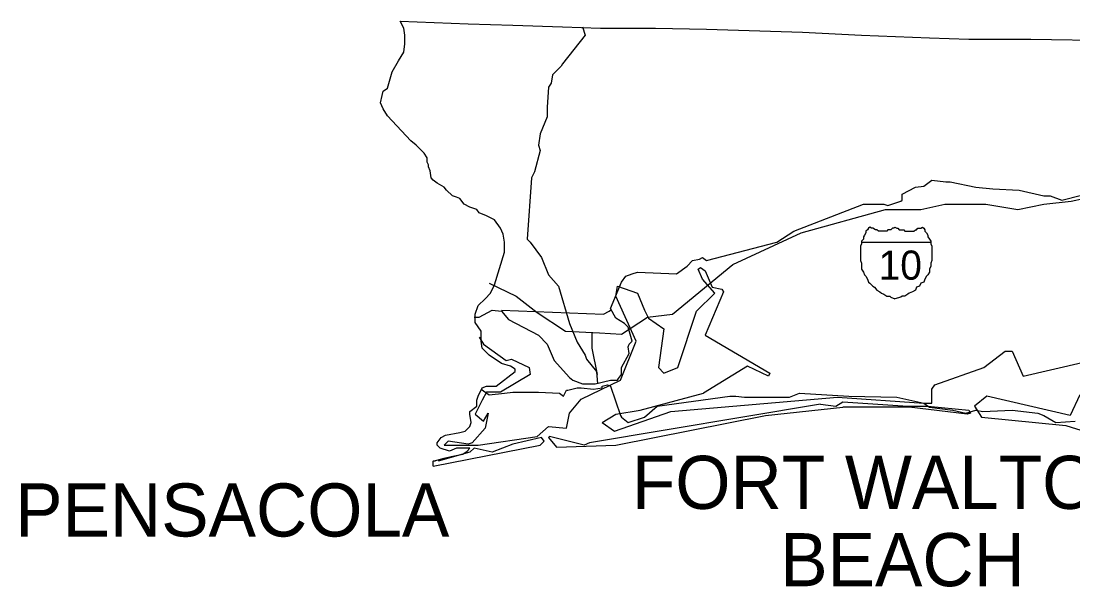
# Model space of a CAD drawing. Extents: x -820.2 to -798.1, y -2199.1 to -2182.2.
# Drawn here: x -808.86 to -807.968, y -2183.531 to -2183.051 of the extents above; entities that cross this region are included whole.
import ezdxf

# ---------------------------------------------------------------- set-up
doc = ezdxf.new("R2010")
doc.units = 0
for name, color, linetype in [('FLMap1', 7, 'Continuous'), ('FLMap2', 7, 'Continuous'), ('FLMap3', 7, 'Continuous'), ('TextMisc', 7, 'Continuous')]:
    doc.layers.add(name, color=color, linetype=linetype)

msp = doc.modelspace()

# ---------------------------------------------------------------- linework, layer by layer
at = {"layer": 'FLMap1'}
msp.add_line((-808.14733, -2183.23888), (-808.08878, -2183.23888), dxfattribs=at)
for points in [[(-808.11905, -2183.22598), (-808.12004, -2183.22697), (-808.12103, -2183.22697), (-808.12252, -2183.22846), (-808.12351, -2183.22846), (-808.125, -2183.22846), (-808.12599, -2183.22945), (-808.12699, -2183.22945), (-808.12847, -2183.22945), (-808.12947, -2183.22945), (-808.13195, -2183.22945), (-808.13294, -2183.22945), (-808.13443, -2183.22846), (-808.13542, -2183.22846), (-808.1379, -2183.22697), (-808.13889, -2183.22697), (-808.14038, -2183.22598), (-808.14137, -2183.22697), (-808.14237, -2183.22846), (-808.14385, -2183.22945), (-808.14385, -2183.23094), (-808.14485, -2183.23292), (-808.14584, -2183.23441), (-808.14584, -2183.2364), (-808.14733, -2183.23788), (-808.14733, -2183.24036), (-808.14832, -2183.24235), (-808.14832, -2183.24483), (-808.14832, -2183.24731), (-808.14832, -2183.24979), (-808.14832, -2183.25178), (-808.14832, -2183.25426), (-808.14733, -2183.25674), (-808.14733, -2183.25922), (-808.14733, -2183.2617), (-808.14584, -2183.26418), (-808.14485, -2183.26666), (-808.14385, -2183.26765), (-808.14237, -2183.27013), (-808.14137, -2183.27261), (-808.14038, -2183.27361), (-808.1379, -2183.27609), (-808.13641, -2183.27708), (-808.13443, -2183.27956), (-808.13195, -2183.28105), (-808.13046, -2183.28204), (-808.12847, -2183.28303), (-808.12599, -2183.28452), (-808.12351, -2183.28452), (-808.12252, -2183.28551), (-808.11905, -2183.287)], [(-808.11905, -2183.22598), (-808.11756, -2183.22697), (-808.11657, -2183.22697), (-808.11558, -2183.22846), (-808.11409, -2183.22846), (-808.11161, -2183.22846), (-808.11061, -2183.22945), (-808.10962, -2183.22945), (-808.10813, -2183.22945), (-808.10714, -2183.22945), (-808.10516, -2183.22945), (-808.10317, -2183.22945), (-808.10168, -2183.22846), (-808.10069, -2183.22846), (-808.0997, -2183.22697), (-808.09722, -2183.22697), (-808.09573, -2183.22598), (-808.09474, -2183.22697), (-808.09375, -2183.22846), (-808.09375, -2183.22945), (-808.09226, -2183.23094), (-808.09127, -2183.23292), (-808.09127, -2183.23441), (-808.08978, -2183.2364), (-808.08878, -2183.23788), (-808.08878, -2183.24036), (-808.08779, -2183.24235), (-808.08779, -2183.24483), (-808.08779, -2183.24731), (-808.08779, -2183.24979), (-808.08779, -2183.25178), (-808.08779, -2183.25426), (-808.08878, -2183.25674), (-808.08878, -2183.25922), (-808.08978, -2183.2617), (-808.08978, -2183.26418), (-808.09127, -2183.26666), (-808.09226, -2183.26765), (-808.09375, -2183.27013), (-808.09474, -2183.27261), (-808.09722, -2183.27361), (-808.09821, -2183.27609), (-808.10069, -2183.27708), (-808.10168, -2183.27956), (-808.10416, -2183.28105), (-808.10714, -2183.28204), (-808.10813, -2183.28303), (-808.11061, -2183.28452), (-808.11309, -2183.28452), (-808.11409, -2183.28551), (-808.11905, -2183.287)]]:
    msp.add_lwpolyline(points, dxfattribs=at)
at = {"layer": 'FLMap2'}
for points in [[(-808.51049, -2183.42889), (-808.51049, -2183.42443), (-808.50106, -2183.42195), (-808.49511, -2183.42046), (-808.48519, -2183.41847), (-808.48171, -2183.41599), (-808.47923, -2183.41351), (-808.49065, -2183.41351), (-808.4966, -2183.41599), (-808.50454, -2183.41351), (-808.50702, -2183.41103), (-808.50702, -2183.40905), (-808.50354, -2183.40458), (-808.50007, -2183.4026), (-808.48767, -2183.40012), (-808.4832, -2183.39912), (-808.47923, -2183.39516), (-808.47824, -2183.39168), (-808.47923, -2183.38474), (-808.47923, -2183.38226), (-808.47328, -2183.37779), (-808.47328, -2183.37283), (-808.47229, -2183.36936), (-808.46882, -2183.36241), (-808.46534, -2183.36092), (-808.46187, -2183.36092), (-808.45691, -2183.36092), (-808.44103, -2183.34852), (-808.44103, -2183.34654), (-808.445, -2183.34405), (-808.45244, -2183.34157), (-808.46286, -2183.33463), (-808.46882, -2183.32868), (-808.46981, -2183.32272), (-808.46981, -2183.31776), (-808.46981, -2183.31429), (-808.47477, -2183.30685), (-808.47477, -2183.2999), (-808.47229, -2183.29246), (-808.46634, -2183.287), (-808.46187, -2183.28204), (-808.4584, -2183.27509), (-808.44996, -2183.24731), (-808.44996, -2183.23888), (-808.45096, -2183.23193), (-808.45344, -2183.22697), (-808.4584, -2183.22002), (-808.46534, -2183.21655), (-808.4713, -2183.21407), (-808.47328, -2183.21109), (-808.47923, -2183.20911), (-808.4842, -2183.20663), (-808.48767, -2183.20167), (-808.49065, -2183.20068), (-808.49412, -2183.19968), (-808.49908, -2183.19472), (-808.50106, -2183.19224), (-808.50702, -2183.18877), (-808.51049, -2183.18629), (-808.51198, -2183.1843), (-808.51297, -2183.17835), (-808.51446, -2183.17488), (-808.51446, -2183.17339), (-808.51545, -2183.17091), (-808.51545, -2183.16743), (-808.51793, -2183.16347), (-808.52488, -2183.15652), (-808.52934, -2183.15305), (-808.54919, -2183.13171), (-808.55266, -2183.12576), (-808.55514, -2183.1208), (-808.55365, -2183.11435), (-808.55266, -2183.11088), (-808.54919, -2183.1084), (-808.54522, -2183.0945), (-808.53976, -2183.08508), (-808.5353, -2183.07764), (-808.5343, -2183.07069), (-808.5343, -2183.06325), (-808.5353, -2183.0573), (-808.53827, -2183.05134)], [(-808.38398, -2183.0563), (-808.3815, -2183.06325), (-808.40085, -2183.08756), (-808.40184, -2183.08954), (-808.40928, -2183.09698), (-808.41027, -2183.10393), (-808.41275, -2183.1074), (-808.41375, -2183.12427), (-808.41375, -2183.12923), (-808.41375, -2183.13271), (-808.4197, -2183.14709), (-808.42119, -2183.15652), (-808.4197, -2183.16099), (-808.42466, -2183.17934), (-808.42714, -2183.1843), (-808.43061, -2183.2364), (-808.42813, -2183.23888), (-808.41871, -2183.25178), (-808.41275, -2183.26666), (-808.40432, -2183.27609), (-808.39489, -2183.30784), (-808.38844, -2183.32371), (-808.3815, -2183.33463), (-808.38051, -2183.3381), (-808.37207, -2183.34852), (-808.37108, -2183.35894)], [(-808.47576, -2183.30238), (-808.4713, -2183.30238), (-808.46038, -2183.29643), (-808.45244, -2183.29742), (-808.44649, -2183.30437), (-808.42119, -2183.31776), (-808.41375, -2183.3252), (-808.40779, -2183.33909), (-808.39489, -2183.35348), (-808.39192, -2183.35596), (-808.38398, -2183.35894), (-808.37306, -2183.35894), (-808.36016, -2183.35596), (-808.35421, -2183.35596), (-808.35322, -2183.35447), (-808.35074, -2183.351), (-808.35074, -2183.34505), (-808.35074, -2183.34505), (-808.34429, -2183.33314), (-808.34528, -2183.32768), (-808.34429, -2183.3252), (-808.34181, -2183.32272), (-808.34528, -2183.31081), (-808.34826, -2183.30784), (-808.3557, -2183.30337), (-808.36016, -2183.29494), (-808.35074, -2183.27261), (-808.34727, -2183.26765), (-808.34181, -2183.26567), (-808.33734, -2183.26418), (-808.3041, -2183.26567), (-808.29517, -2183.25922), (-808.29071, -2183.25426), (-808.28475, -2183.25326), (-808.28227, -2183.25178), (-808.2788, -2183.25426), (-808.21927, -2183.23888), (-808.20488, -2183.22945), (-808.14584, -2183.20663), (-808.12847, -2183.20663), (-808.125, -2183.20762), (-808.11409, -2183.20415), (-808.11309, -2183.20316), (-808.11309, -2183.19819), (-808.10168, -2183.19224), (-808.09474, -2183.19125), (-808.08779, -2183.18629), (-808.07589, -2183.18778), (-808.07241, -2183.18778), (-808.05058, -2183.19224), (-808.0362, -2183.19373)], [(-808.0362, -2183.19373), (-808.01387, -2183.19472), (-807.99303, -2183.19968), (-807.98758, -2183.19968), (-807.97765, -2183.20316), (-807.94441, -2183.19472)], [(-808.30311, -2183.34505), (-808.28723, -2183.29742), (-808.27185, -2183.28204), (-808.28227, -2183.27013), (-808.28575, -2183.2617), (-808.28376, -2183.26021), (-808.27979, -2183.26319), (-808.27384, -2183.27708), (-808.2659, -2183.27857), (-808.26441, -2183.28105), (-808.27979, -2183.31776)], [(-808.35173, -2183.35596), (-808.33834, -2183.32272), (-808.3557, -2183.28452), (-808.35421, -2183.27609), (-808.33734, -2183.28204), (-808.33139, -2183.29643), (-808.32792, -2183.30337), (-808.31502, -2183.3123), (-808.31948, -2183.34505), (-808.31502, -2183.35001), (-808.30311, -2183.34505)], [(-808.45244, -2183.29643), (-808.36612, -2183.2999), (-808.36116, -2183.29742), (-808.36016, -2183.29643)], [(-808.4713, -2183.31925), (-808.46782, -2183.3252), (-808.44847, -2183.33909), (-808.44401, -2183.3381), (-808.42913, -2183.34505), (-808.42813, -2183.351), (-808.45344, -2183.36588), (-808.46534, -2183.36588), (-808.46882, -2183.37283), (-808.47477, -2183.38474), (-808.46782, -2183.39069), (-808.46385, -2183.38374), (-808.46634, -2183.39664), (-808.47725, -2183.40905), (-808.48072, -2183.41004), (-808.49759, -2183.40756), (-808.50106, -2183.41103), (-808.47229, -2183.41103), (-808.42218, -2183.40359), (-808.41275, -2183.39516), (-808.39737, -2183.39664), (-808.39489, -2183.38374), (-808.38497, -2183.37184), (-808.35173, -2183.35596)], [(-808.27979, -2183.31776), (-808.22522, -2183.35001), (-808.22621, -2183.35249), (-808.24407, -2183.34405), (-808.28128, -2183.36688)], [(-808.16767, -2183.37035), (-808.09474, -2183.37531), (-808.08779, -2183.37531), (-808.08779, -2183.3634), (-808.08531, -2183.35993), (-808.04364, -2183.34505), (-808.02578, -2183.33116), (-808.01982, -2183.33116), (-808.0104, -2183.35249), (-807.9335, -2183.33463)], [(-808.46981, -2183.3634), (-808.46286, -2183.36837), (-808.44996, -2183.36688), (-808.44302, -2183.36588), (-808.42119, -2183.36588), (-808.40333, -2183.36688), (-808.39985, -2183.36936), (-808.39737, -2183.3644), (-808.39638, -2183.3644), (-808.38844, -2183.36241), (-808.38497, -2183.36241), (-808.37455, -2183.3634), (-808.36711, -2183.36241), (-808.36711, -2183.36092), (-808.36265, -2183.35993), (-808.36016, -2183.36092), (-808.36016, -2183.36092), (-808.35173, -2183.38573), (-808.35074, -2183.38722), (-808.34528, -2183.39168), (-808.33139, -2183.38722), (-808.32047, -2183.37779), (-808.25896, -2183.36936), (-808.25399, -2183.36936), (-808.24655, -2183.37035), (-808.20835, -2183.37035), (-808.19992, -2183.36688), (-808.15824, -2183.36936), (-808.11756, -2183.37035), (-808.09474, -2183.37531), (-808.08978, -2183.37878), (-808.06993, -2183.38126), (-808.05902, -2183.38374), (-808.05058, -2183.38126), (-808.04463, -2183.38226), (-808.01982, -2183.38126), (-807.99799, -2183.38374), (-807.99303, -2183.38573), (-807.98261, -2183.39168)], [(-808.36711, -2183.39168), (-808.3557, -2183.38474), (-808.33486, -2183.38126), (-808.28128, -2183.36688)], [(-808.35669, -2183.39912), (-808.30906, -2183.38226), (-808.16767, -2183.37035)], [(-807.96227, -2183.36837), (-807.97071, -2183.38573), (-808.04116, -2183.36936), (-808.05158, -2183.37779), (-808.04562, -2183.38722), (-807.97418, -2183.39416), (-807.89629, -2183.41847)], [(-808.18206, -2183.3763), (-808.37802, -2183.40905), (-808.38249, -2183.41103), (-808.41176, -2183.40359), (-808.41275, -2183.40458), (-808.40581, -2183.41252), (-808.3557, -2183.41103), (-808.22869, -2183.38573), (-808.1632, -2183.37878)], [(-808.18206, -2183.3763), (-808.16916, -2183.37779), (-808.1632, -2183.37432), (-808.10813, -2183.37779), (-808.09127, -2183.37779), (-808.05654, -2183.38126), (-808.05505, -2183.38374), (-808.05802, -2183.38474), (-808.10714, -2183.37878), (-808.1632, -2183.37878)], [(-808.36711, -2183.39168), (-808.35669, -2183.39912)], [(-807.98261, -2183.39168), (-807.96624, -2183.39069)], [(-808.51049, -2183.42889), (-808.4197, -2183.41103), (-808.41623, -2183.40756), (-808.41871, -2183.40458), (-808.44302, -2183.41004), (-808.46038, -2183.41699), (-808.47576, -2183.41351), (-808.47923, -2183.41699), (-808.50603, -2183.42443)], [(-808.50851, -2183.42443), (-808.51049, -2183.42443)]]:
    msp.add_lwpolyline(points, dxfattribs=at)
at = {"layer": 'FLMap3'}
for points in [[(-808.53827, -2183.05134), (-808.48072, -2183.05382), (-808.44302, -2183.05481), (-808.40085, -2183.0563), (-808.3686, -2183.0573), (-808.32196, -2183.0573), (-808.2788, -2183.05829), (-808.19744, -2183.06077), (-808.14733, -2183.06325), (-808.08978, -2183.06573), (-808.05654, -2183.06672), (-808.00395, -2183.06672), (-807.9335, -2183.06771)], [(-808.46286, -2183.27361), (-808.44004, -2183.28452), (-808.42218, -2183.29841), (-808.39837, -2183.31429), (-808.36959, -2183.31578), (-808.35074, -2183.31677), (-808.32891, -2183.30238), (-808.30758, -2183.2999), (-808.25647, -2183.25773), (-808.19843, -2183.23094), (-808.12699, -2183.21109), (-808.09722, -2183.21109), (-808.07688, -2183.20663), (-808.04215, -2183.20663), (-808.01486, -2183.21109), (-807.99303, -2183.20663), (-807.96971, -2183.20415), (-807.93846, -2183.1972)], [(-808.37108, -2183.351), (-808.37554, -2183.32868), (-808.37554, -2183.31578)]]:
    msp.add_lwpolyline(points, dxfattribs=at)

# ---------------------------------------------------------------- texts
at = {"layer": 'TextMisc'}
for s, height, p in [('10', 0.024695, (-808.13294, -2183.27063)), ('FORT WALTON', 0.045, (-808.34197, -2183.46497)), ('PENSACOLA', 0.045, (-808.86459, -2183.48839)), ('BEACH', 0.045, (-808.21623, -2183.53053))]:
    msp.add_text(s, height=height, dxfattribs=at).set_placement(p)

doc.saveas('drawing.dxf')
